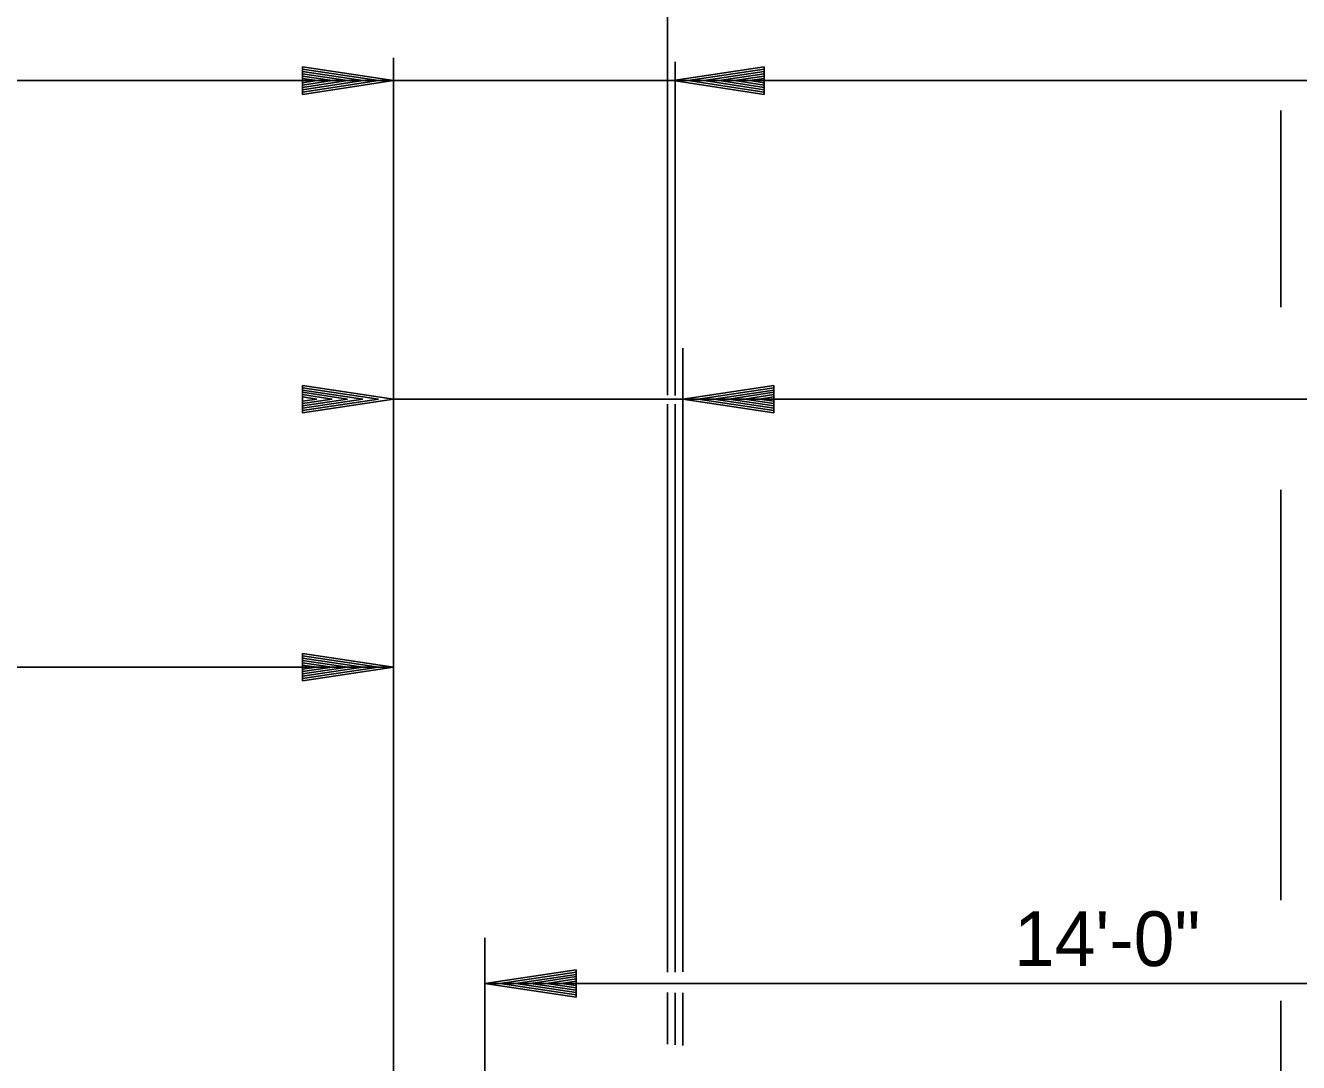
# Model space of a CAD drawing. Extents: x 2478 to 3210, y 439 to 841.
# Drawn here: x 3040.31 to 3068.23, y 608.39 to 631.14 of the extents above; entities that cross this region are included whole.
import ezdxf

# ---------------------------------------------------------------- set-up
doc = ezdxf.new("R2010")
doc.units = 0
doc.layers.add('R_Annotation', color=7, linetype='Continuous')
doc.layers.add('R_Dimension', color=7, linetype='Continuous')

msp = doc.modelspace()

# ---------------------------------------------------------------- linework, layer by layer
at = {"layer": 'R_Dimension'}
for p, q in [((3054.39, 630.429), (3054.39, 636.027)), ((3048.387, 610.625), (3048.387, 630.429)), ((3054.39, 623.033), (3054.39, 630.429)), ((3046.387, 630.229), (3048.387, 629.929)), ((3046.387, 630.229), (3046.387, 629.629)), ((3046.387, 630.179), (3048.053, 629.929)), ((3056.515, 630.229), (3054.515, 629.929)), ((3054.557, 623.025), (3054.557, 630.344)), ((3056.515, 630.179), (3054.849, 629.929)), ((3056.515, 629.629), (3056.515, 630.229)), ((3008.387, 629.929), (3048.387, 629.929)), ((3046.387, 630.128), (3047.709, 629.929)), ((3046.387, 630.078), (3047.376, 629.929)), ((3046.387, 630.026), (3047.037, 629.929)), ((3046.387, 629.976), (3046.703, 629.929)), ((3046.387, 629.629), (3048.387, 629.929)), ((3046.387, 629.831), (3047.037, 629.929)), ((3046.387, 629.73), (3047.709, 629.929)), ((3046.387, 629.679), (3048.053, 629.929)), ((3046.387, 629.78), (3047.376, 629.929)), ((3046.387, 629.882), (3046.703, 629.929)), ((3048.387, 629.929), (3102.23, 629.929)), ((3056.515, 629.629), (3054.515, 629.929)), ((3056.515, 629.679), (3054.849, 629.929)), ((3056.515, 630.128), (3055.193, 629.929)), ((3056.515, 629.73), (3055.193, 629.929)), ((3056.515, 630.078), (3055.526, 629.929)), ((3056.515, 629.78), (3055.526, 629.929)), ((3056.515, 630.027), (3055.865, 629.929)), ((3056.515, 629.832), (3055.865, 629.929)), ((3056.515, 629.976), (3056.199, 629.929)), ((3056.515, 629.882), (3056.199, 629.929)), ((3067.845, 624.959), (3067.845, 629.274)), ((3054.728, 610.377), (3054.728, 624.064)), ((3046.387, 623.244), (3048.387, 622.944)), ((3046.387, 623.244), (3046.387, 622.644)), ((3046.387, 623.194), (3048.053, 622.944)), ((3056.728, 623.244), (3054.728, 622.944)), ((3056.728, 623.194), (3055.062, 622.944)), ((3056.728, 622.644), (3056.728, 623.244)), ((3046.387, 623.143), (3047.709, 622.944)), ((3046.387, 623.093), (3047.376, 622.944)), ((3046.387, 623.041), (3047.037, 622.944)), ((3046.387, 622.991), (3046.703, 622.944)), ((3046.387, 622.644), (3048.387, 622.944)), ((3046.387, 622.846), (3047.037, 622.944)), ((3046.387, 622.745), (3047.709, 622.944)), ((3046.387, 622.694), (3048.053, 622.944)), ((3046.387, 622.795), (3047.376, 622.944)), ((3046.387, 622.897), (3046.703, 622.944)), ((3048.387, 622.944), (3102.23, 622.944)), ((3056.728, 622.644), (3054.728, 622.944)), ((3056.728, 622.694), (3055.062, 622.944)), ((3056.728, 623.143), (3055.406, 622.944)), ((3056.728, 622.745), (3055.406, 622.944)), ((3056.728, 623.093), (3055.739, 622.944)), ((3056.728, 622.795), (3055.739, 622.944)), ((3056.728, 623.042), (3056.078, 622.944)), ((3056.728, 622.847), (3056.078, 622.944)), ((3056.728, 622.991), (3056.412, 622.944)), ((3056.728, 622.897), (3056.412, 622.944)), ((3054.39, 610.37), (3054.39, 622.835)), ((3054.557, 610.375), (3054.557, 622.835)), ((3067.845, 611.954), (3067.845, 620.95)), ((3046.387, 617.363), (3048.387, 617.063)), ((3046.387, 617.363), (3046.387, 616.763)), ((3046.387, 617.313), (3048.053, 617.063)), ((3008.387, 617.063), (3048.387, 617.063)), ((3046.387, 617.262), (3047.709, 617.063)), ((3046.387, 617.212), (3047.376, 617.063)), ((3046.387, 617.16), (3047.037, 617.063)), ((3046.387, 617.11), (3046.703, 617.063)), ((3046.387, 616.763), (3048.387, 617.063)), ((3046.387, 616.965), (3047.037, 617.063)), ((3046.387, 616.864), (3047.709, 617.063)), ((3046.387, 616.813), (3048.053, 617.063)), ((3046.387, 616.914), (3047.376, 617.063)), ((3046.387, 617.016), (3046.703, 617.063)), ((3050.387, 597.431), (3050.387, 611.125)), ((3048.387, 610.625), (3048.387, 606.892)), ((3052.387, 610.425), (3050.387, 610.125)), ((3052.387, 610.375), (3050.721, 610.125)), ((3052.387, 610.324), (3051.065, 610.125)), ((3052.387, 609.825), (3052.387, 610.425)), ((3078.387, 610.125), (3050.387, 610.125)), ((3052.387, 609.825), (3050.387, 610.125)), ((3052.387, 609.875), (3050.721, 610.125)), ((3052.387, 609.926), (3051.065, 610.125)), ((3052.387, 610.274), (3051.398, 610.125)), ((3052.387, 609.976), (3051.398, 610.125)), ((3052.387, 610.223), (3051.737, 610.125)), ((3052.387, 610.028), (3051.737, 610.125)), ((3052.387, 610.172), (3052.071, 610.125)), ((3052.387, 610.078), (3052.071, 610.125)), ((3054.39, 608.796), (3054.39, 609.928)), ((3054.557, 608.775), (3054.557, 609.921)), ((3054.728, 608.767), (3054.728, 609.921)), ((3067.845, 601.641), (3067.845, 609.746))]:
    msp.add_line(p, q, dxfattribs=at)

# ---------------------------------------------------------------- texts
at = {"layer": 'R_Annotation'}
msp.add_text('14\'-0"', height=1.2, dxfattribs=at).set_placement((3061.991, 610.506))

doc.saveas('drawing.dxf')
